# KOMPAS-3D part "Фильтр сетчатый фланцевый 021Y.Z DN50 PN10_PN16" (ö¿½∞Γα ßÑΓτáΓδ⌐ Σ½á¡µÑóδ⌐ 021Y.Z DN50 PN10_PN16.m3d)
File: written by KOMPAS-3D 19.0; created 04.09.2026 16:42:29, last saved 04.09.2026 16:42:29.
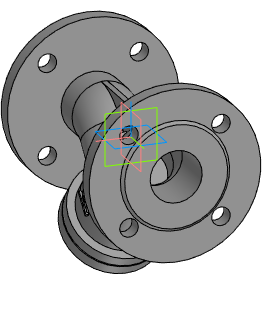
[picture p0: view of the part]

Document properties: Автор: Энергия; Полное имя файла: Z:\3.Личные\sachek\Dendor\_3D для проектировщиков\8.1 Фильтр сетчатый 021Y.Z\021Y.Z_STP\Фильтр сетчатый фланцевый 021Y.Z DN50 PN10_PN16.m3d

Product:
- Part/product: Фильтр сетчатый фланцевый 021Y.Z DN50 PN10_PN16

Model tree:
1. Операция без истории:1  (labels: Фильтр сетчатый фланцевый 021Y.Z DN50 PN10_PN16)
